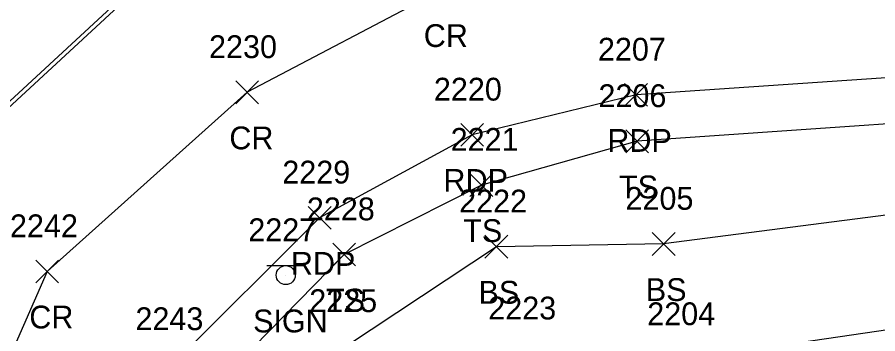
# Model space of a CAD drawing. Extents: x 49137 to 50946, y 9590 to 10709.
# Drawn here: x 49987.7 to 50063, y 10102.1 to 10129.9 of the extents above; entities that cross this region are included whole.
import ezdxf

# ---------------------------------------------------------------- set-up
doc = ezdxf.new("R2010")
doc.units = 0
for name, color, linetype in [('L_A', 7, 'Continuous'), ('L_I', 7, 'Continuous'), ('L_TIC', 7, 'Continuous'), ('LELB', 7, 'Continuous'), ('P_A', 7, 'Continuous'), ('P_I', 7, 'Continuous'), ('P_TIC', 7, 'Continuous'), ('PET', 7, 'Continuous'), ('PRC', 7, 'Continuous'), ('RC', 7, 'Continuous'), ('S_A', 7, 'Continuous'), ('S_I', 7, 'Continuous'), ('SSGN', 7, 'Continuous')]:
    doc.layers.add(name, color=color, linetype=linetype)

msp = doc.modelspace()

# ---------------------------------------------------------------- linework, layer by layer
at = {"layer": 'L_TIC'}
for points in [[(50040.967, 10117.998), (50042.967, 10119.998)], [(50042.967, 10117.998), (50040.967, 10119.998)], [(50027.317, 10114.165), (50029.317, 10116.165)], [(50029.317, 10114.165), (50027.317, 10116.165)], [(50028.628, 10108.759), (50030.628, 10110.759)], [(50030.628, 10108.759), (50028.628, 10110.759)], [(50043.282, 10108.996), (50045.282, 10110.996)], [(50045.282, 10108.996), (50043.282, 10110.996)], [(50015.289, 10108.072), (50017.289, 10110.072)], [(50017.289, 10108.072), (50015.289, 10110.072)]]:
    msp.add_lwpolyline(points, dxfattribs=at)
at = {"layer": 'LELB'}
for points in [[(50533.21, 10111.605), (50454.371, 10111.295), (50403.703, 10114.567), (50361.619, 10116.937), (50329.481, 10118.313), (50280.684, 10120.525), (50237.293, 10122.216), (50191.559, 10123.072), (50146.806, 10122.773), (50115.16, 10122.306), (50083.391, 10121.864), (50041.967, 10118.998), (50028.317, 10115.165), (50016.289, 10109.072), (50004.383, 10096.894), (49998.689, 10083.532), (49995.827, 10073.633), (49998.741, 10070.586), (50003.659, 10071.93), (50011.007, 10077.239), (50017.534, 10082.527), (50020.315, 10080.947)], [(50644.742, 10103.973), (50611.952, 10100.778), (50591.588, 10097.048), (50585.387, 10096.694), (50579.074, 10095.776), (50533.17, 10102.578), (50499.54, 10106.388), (50453.773, 10106.952), (50403.465, 10111.124), (50360.868, 10113.768), (50329.071, 10115.48), (50280.618, 10115.792), (50236.612, 10117.169), (50191.06, 10116.346), (50147.051, 10116.336), (50114.684, 10115.107), (50083.467, 10115.051), (50044.282, 10109.996), (50029.628, 10109.759), (50016.498, 10101.022), (50008.235, 10092.101), (50002.089, 10081.322)], [(50656.331, 10076.988), (50615.693, 10084.114), (50585.229, 10087.973), (50578.177, 10088.239), (50532.061, 10091.891), (50499.01, 10096.848), (50452.628, 10097.836), (50403.288, 10103.356), (50360.445, 10105.851), (50327.916, 10107.016), (50280.055, 10107.276), (50236.472, 10108.204), (50190.707, 10107.877), (50147.643, 10108.128), (50115.133, 10105.803), (50083.068, 10105.279), (50046.186, 10099.874), (50032.18, 10100.376), (50021.321, 10094.179), (50013.135, 10086.724), (50006.194, 10078.9), (50001.559, 10073.092), (49999.891, 10073.287), (50002.089, 10081.322)]]:
    msp.add_lwpolyline(points, dxfattribs=at)
at = {"layer": 'P_TIC'}
for points in [[(50006.805, 10122.297), (50008.805, 10124.297)], [(50008.805, 10122.297), (50006.805, 10124.297)], [(50040.867, 10122.075), (50042.867, 10124.075)], [(50042.867, 10122.075), (50040.867, 10124.075)], [(50026.505, 10118.57), (50028.505, 10120.57)], [(50028.505, 10118.57), (50026.505, 10120.57)], [(50013.145, 10111.296), (50015.145, 10113.296)], [(50015.145, 10111.296), (50013.145, 10113.296)], [(49989.279, 10106.587), (49991.279, 10108.587)], [(49991.279, 10106.587), (49989.279, 10108.587)]]:
    msp.add_lwpolyline(points, dxfattribs=at)
at = {"layer": 'PET'}
for points in [[(50500, 10146.803), (50482.824, 10146.596), (50451.943, 10142.575), (50406.356, 10149.875), (50391.036, 10152.294), (50366.967, 10154.835), (50332.971, 10157.453), (50281.747, 10161.159), (50239.768, 10163.197), (50191.306, 10163.258), (50147.424, 10160.548), (50119.041, 10158.144), (50090.984, 10156.228), (50087.122, 10154.93), (50074.588, 10152.393), (50039.424, 10148.744), (50022.281, 10145.278), (50001.488, 10135.468), (49981.426, 10116.921), (49974.218, 10104.512), (49968.544, 10090.521), (49966.026, 10076.927), (49965.371, 10068.985)], [(50664.039, 10109.02), (50639.147, 10120.648), (50622.164, 10120.013), (50585.926, 10117.585), (50533.387, 10115.346), (50500.143, 10114.934), (50454.131, 10114.71), (50404.199, 10117.574), (50361.953, 10120.552), (50329.605, 10122.428), (50280.881, 10124.623), (50237.668, 10126.173), (50191.617, 10126.612), (50146.368, 10126.55), (50115.334, 10126.086), (50083.529, 10125.91), (50041.867, 10123.075), (50027.505, 10119.57), (50014.145, 10112.296), (50001.27, 10099.439), (49993.667, 10082.305), (49991.684, 10072.985), (49993.667, 10063.344)]]:
    msp.add_lwpolyline(points, dxfattribs=at)
at = {"layer": 'PRC'}
msp.add_lwpolyline([(50496.817, 10130.355), (50455.322, 10129.806), (50404.409, 10131.956), (50361.938, 10134.122), (50331.696, 10136.067), (50280.642, 10137.312), (50238.724, 10140.088), (50190.79, 10138.958), (50146.004, 10140.156), (50115.75, 10139.222), (50082.655, 10138.746), (50040.307, 10135.561), (50024.837, 10132.269), (50007.805, 10123.297), (49990.279, 10107.587), (49982.883, 10090.76), (49978.98, 10075.387)], dxfattribs=at)
at = {"layer": 'RC'}
msp.add_lwpolyline([(50090.984, 10156.228), (50086.802, 10155.012), (50074.635, 10152.68), (50039.404, 10148.944), (50022.233, 10145.541), (50001.273, 10135.771), (49981.184, 10117.18), (49973.858, 10104.886), (49968.286, 10090.59), (49965.755, 10076.904), (49965.095, 10068.882)], dxfattribs=at)
at = {"layer": 'SSGN'}
for p, q in [((50009.53, 10108.096), (50012.863, 10108.096)), ((50011.177, 10107.262), (50011.177, 10107.262))]:
    msp.add_line(p, q, dxfattribs=at)
msp.add_circle((50011.177, 10107.262), 0.833, dxfattribs=at)

# ---------------------------------------------------------------- texts
at = {"layer": 'L_A'}
for s, p in [('TS', (50040.377, 10113.998)), ('TS', (50026.726, 10110.165)), ('BS', (50028.069, 10104.759)), ('BS', (50042.723, 10104.996)), ('TS', (50014.698, 10104.072))]:
    msp.add_text(s, height=2, dxfattribs=at).set_placement(p)
at = {"layer": 'L_I'}
for s, p in [('2206', (50038.574, 10121.998)), ('2221', (50025.624, 10118.165)), ('2205', (50040.944, 10112.996)), ('2228', (50013.029, 10112.072)), ('2222', (50026.368, 10112.759)), ('2225', (50013.238, 10104.022)), ('2223', (50028.92, 10103.376)), ('2204', (50042.848, 10102.874))]:
    msp.add_text(s, height=2, dxfattribs=at).set_placement(p)
at = {"layer": 'P_A'}
for s, p in [('CR', (50023.27, 10127.269)), ('CR', (50006.238, 10118.297)), ('RDP', (50039.356, 10118.075)), ('RDP', (50024.993, 10114.57)), ('RDP', (50011.633, 10107.296)), ('CR', (49988.712, 10102.587))]:
    msp.add_text(s, height=2, dxfattribs=at).set_placement(p)
at = {"layer": 'P_I'}
for s, p in [('2230', (50004.459, 10126.297)), ('2207', (50038.529, 10126.075)), ('2220', (50024.158, 10122.57)), ('2229', (50010.877, 10115.296)), ('2242', (49987.019, 10110.587)), ('2243', (49998.01, 10102.439))]:
    msp.add_text(s, height=2, dxfattribs=at).set_placement(p)
at = {"layer": 'S_A'}
msp.add_text('SIGN', height=2, dxfattribs=at).set_placement((50008.315, 10102.242))
at = {"layer": 'S_I'}
msp.add_text('2227', height=2, dxfattribs=at).set_placement((50007.898, 10110.242))

doc.saveas('drawing.dxf')
